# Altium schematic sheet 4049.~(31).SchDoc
size A4
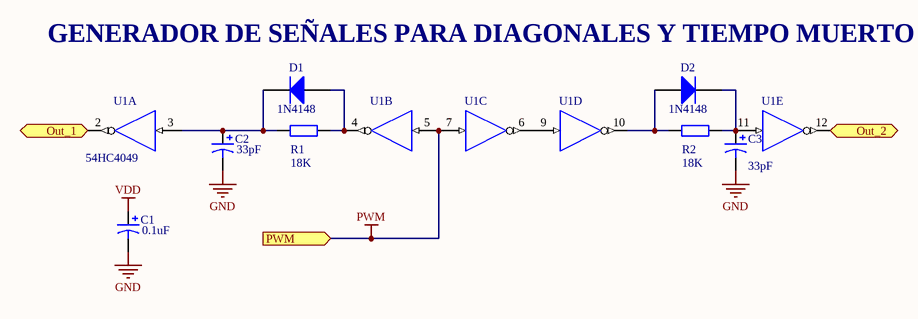
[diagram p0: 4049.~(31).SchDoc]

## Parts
C1  value 0.1uF  [CAPPR2.5-6.3X5]  (hidden comment: Cap Pol1 0.1u)
C2  value 33pF  [CAPPR2.5-6.3X5]  (hidden comment: Cap Pol1)
C3  value 33pF  [CAPPR2.5-6.3X5]  (hidden comment: Cap Pol1)
D1  value 1N4148  [DO-204AL]  (hidden comment: Diode1)
D2  value 1N4148  [DO-204AL]  (hidden comment: Diode1)
R1  18k  [AXIAL-0.3]
R2  18k  [AXIAL-0.3]
U1  value 54HC4049  [620-09]  (hidden comment: MC54HC4049J)  (parts A,B,C,D,E of 6)

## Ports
Out_1 (out), Out_2 (out), PWM (in)

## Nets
GND: C1.2 C2.2 C3.2 U1.8(GND)
PWM: U1.5(A) U1.7(A) ; port PWM
VDD: C1.1 U1.1(VDD)
Out_1: U1.2(Y) ; port Out_1
Out_2: U1.12(Y) ; port Out_2
NetC2_1: C2.1 D1.2(K) R1.1 U1.3(A)
NetC3_1: C3.1 D2.2(K) R2.2 U1.11(A)
NetD1_1: D1.1(A) R1.2 U1.4(Y)
NetD2_1: D2.1(A) R2.1 U1.10(Y)
NetU1_6: U1.6(Y) U1.9(A)

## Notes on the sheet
- GENERADOR DE SEÑALES PARA DIAGONALES Y TIEMPO MUERTO

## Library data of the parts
C1-C3 = Cap Pol1: Polarized Capacitor (Radial)
D1 D2 = Diode: 1N4148
R1 R2 = Res2: Resistor
U1 = MC54HC4049J: Hex Inverting Buffer/Logic-Level Down Converter; Note: Pins 13 & 16 are NC and not drawn.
